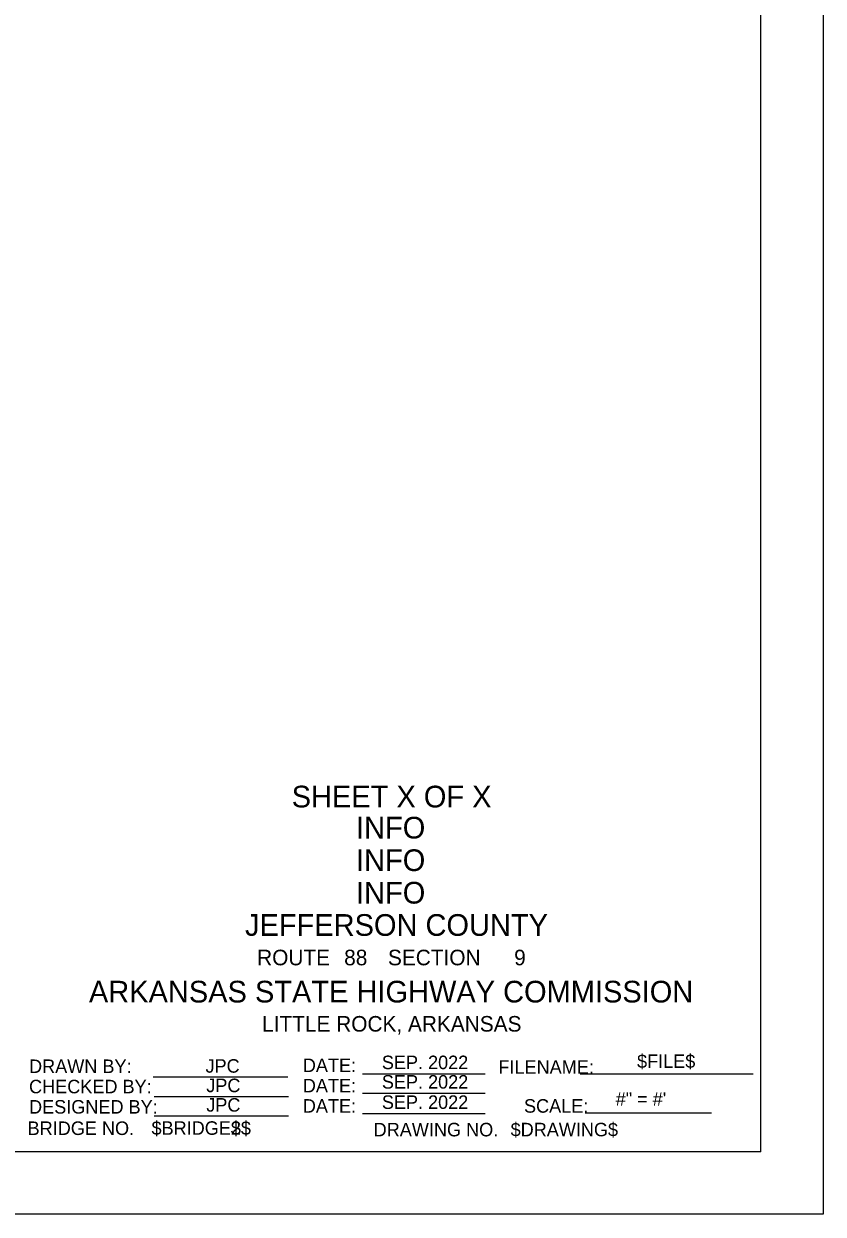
# Model space of a CAD drawing. Extents: x 16 to 1228743, y 11 to 152440.
# Drawn here: x 17.875 to 18.49, y 10.71 to 11.626 of the extents above; entities that cross this region are included whole.
import ezdxf

# ---------------------------------------------------------------- set-up
doc = ezdxf.new("R2010")
doc.units = 0
for name, color, linetype in [('B_Bridge1', 7, 'Continuous'), ('B_Bridge2', 7, 'Continuous'), ('B_Copy In', 7, 'Continuous'), ('B_County and Route', 7, 'Continuous'), ('B_Text', 7, 'Continuous'), ('B_Title Text', 7, 'Continuous'), ('R_Border', 7, 'Continuous')]:
    doc.layers.add(name, color=color, linetype=linetype)

msp = doc.modelspace()

# ---------------------------------------------------------------- linework, layer by layer
at = {"layer": 'B_Text'}
for p, q in [((18.13563, 10.81768), (18.23013, 10.81768)), ((18.30322, 10.81768), (18.43627, 10.81768)), ((17.97453, 10.81518), (18.07813, 10.81518)), ((17.97513, 10.80018), (18.07873, 10.80018)), ((18.13563, 10.80268), (18.23013, 10.80268)), ((18.13563, 10.80268), (18.23013, 10.80268)), ((17.97513, 10.78518), (18.07873, 10.78518)), ((18.13563, 10.78705), (18.23013, 10.78705)), ((18.3071, 10.78768), (18.40423, 10.78768))]:
    msp.add_line(p, q, dxfattribs=at)
at = {"layer": 'R_Border'}
for q in [(18.44224, 12.49478), (15.7833, 10.75758)]:
    msp.add_line((18.44224, 10.75758), q, dxfattribs=at)
msp.add_lwpolyline([(15.65697, 12.54285), (18.49031, 12.54285), (18.49031, 10.70951), (15.65697, 10.70951)], close=True, dxfattribs=at)

# ---------------------------------------------------------------- texts
at = {"layer": 'B_Bridge1'}
msp.add_text('$BRIDGE$', height=0.0104, dxfattribs=at).set_placement((17.97316, 10.77064))
at = {"layer": 'B_Bridge2'}
msp.add_text('$BRIDGE2$', height=0.0104, dxfattribs=at).set_placement((17.97316, 10.77064))
at = {"layer": 'B_Copy In'}
for s, height, p in [('SHEET X OF X', 0.0167, (18.08106, 11.02274)), ('INFO', 0.0167, (18.1306, 10.99881)), ('INFO', 0.0167, (18.1306, 10.97376)), ('INFO', 0.0167, (18.1306, 10.94871)), ('JPC', 0.0104, (18.01471, 10.81848)), ('SEP. 2022', 0.0104, (18.1505, 10.82121)), ('SEP. 2022', 0.0104, (18.1505, 10.80621)), ('JPC', 0.0104, (18.01531, 10.80348)), ('JPC', 0.0104, (18.01531, 10.78848)), ('SEP. 2022', 0.0104, (18.1505, 10.79059)), ('#" = #\'', 0.0104, (18.33054, 10.79304))]:
    msp.add_text(s, height=height, dxfattribs=at).set_placement(p)
at = {"layer": 'B_County and Route'}
for s, height, p in [('JEFFERSON COUNTY', 0.0167, (18.04513, 10.92386)), ('88', 0.012, (18.12148, 10.90117)), ('9', 0.012, (18.25236, 10.90117))]:
    msp.add_text(s, height=height, dxfattribs=at).set_placement(p)
at = {"layer": 'B_Text'}
for s, height, p in [('DRAWN BY:', 0.010417, (17.87883, 10.81822)), ('DATE:', 0.010417, (18.08963, 10.81893)), ('FILENAME:', 0.010417, (18.24021, 10.81768)), ('CHECKED BY:', 0.0104167, (17.87883, 10.80259)), ('DATE:', 0.010417, (18.08963, 10.8033)), ('DESIGNED BY:', 0.0104167, (17.87883, 10.78697)), ('DATE:', 0.010417, (18.08963, 10.78768)), ('SCALE:', 0.010417, (18.25993, 10.78768)), ('BRIDGE NO.', 0.010417, (17.8777, 10.7705)), ('DRAWING NO.', 0.0104166, (18.14416, 10.76944))]:
    msp.add_text(s, height=height, dxfattribs=at).set_placement(p)
at = {"layer": 'B_Title Text'}
for s, height, p in [('ROUTE          SECTION ', 0.012, (18.05444, 10.90117)), ('ARKANSAS STATE HIGHWAY COMMISSION', 0.0167, (17.92495, 10.87253)), ('LITTLE ROCK, ARKANSAS', 0.012, (18.05826, 10.8501))]:
    msp.add_text(s, height=height, dxfattribs=at).set_placement(p)
at = {"layer": 'R_Border'}
for s, p in [('$FILE$', (18.347, 10.82212)), ('$DRAWING$', (18.24965, 10.76948))]:
    msp.add_text(s, height=0.0104, dxfattribs=at).set_placement(p)

doc.saveas('drawing.dxf')
